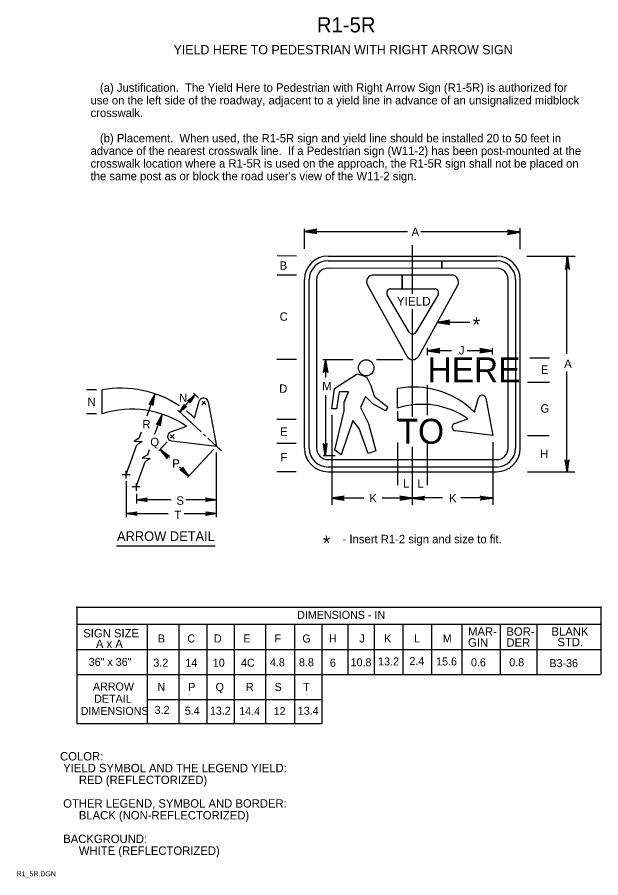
# Model space of a CAD drawing. Extents: x 0.013 to 0.186, y 0.004 to 0.259.
import ezdxf

# ---------------------------------------------------------------- set-up
doc = ezdxf.new("R2010")
doc.units = 0
for name, color, linetype in [('1', 7, 'Continuous'), ('2', 7, 'Continuous'), ('3', 7, 'Continuous')]:
    doc.layers.add(name, color=color, linetype=linetype)

# ---------------------------------------------------------------- blocks, each defined once
blk = doc.blocks.new('RARROW')
at = {"layer": '3'}
for p, q in [((-2.156, 0.28500000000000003), (-2.2665, 0.384625)), ((-2.2665, 0.384625), (0, 0)), ((0, 0), (-2.2665, -0.379125)), ((-2.156, 0.28500000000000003), (-2.075625, 0.12075)), ((0, 0), (-2.156, 0.28500000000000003)), ((-2.14975, -0.2705), (0, 0)), ((-2.075625, 0.12075), (0, 0)), ((0, 0), (-2.074, -0.108)), ((-2.2665, -0.379125), (-2.14975, -0.2705)), ((-2.074, -0.108), (-2.14975, -0.2705))]:
    blk.add_line(p, q, dxfattribs=at)

msp = doc.modelspace()

# ---------------------------------------------------------------- linework, layer by layer
at = {"layer": '1'}
for p, q in [((0.1299704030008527, 0.19165034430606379), (0.1299704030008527, 0.17719405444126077)), ((0.10497040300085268, 0.18840013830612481), (0.15497040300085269, 0.18840013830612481)), ((0.10497040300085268, 0.18700013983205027), (0.13877004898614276, 0.18700013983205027)), ((0.13877004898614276, 0.18470013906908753), (0.13877004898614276, 0.18700013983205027)), ((0.13877004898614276, 0.18700013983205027), (0.15497040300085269, 0.18700013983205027)), ((0.13877004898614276, 0.18700013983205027), (0.13877004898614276, 0.18470013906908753)), ((0.17583661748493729, 0.159368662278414), (0.17583661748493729, 0.1883907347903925)), ((0.13877004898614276, 0.18470013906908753), (0.10497040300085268, 0.18480013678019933)), ((0.15497040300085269, 0.18480013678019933), (0.13877004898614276, 0.18470013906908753)), ((0.09797040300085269, 0.1314001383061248), (0.09797040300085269, 0.1814001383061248)), ((0.0993704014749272, 0.1314001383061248), (0.0993704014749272, 0.1814001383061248)), ((0.10157040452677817, 0.1814001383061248), (0.10157040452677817, 0.1314001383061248)), ((0.12695739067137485, 0.18275925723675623), (0.11844506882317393, 0.18275925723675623)), ((0.12695739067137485, 0.18275925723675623), (0.12695739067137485, 0.1786672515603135)), ((0.12695739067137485, 0.1786672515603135), (0.12695739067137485, 0.18275925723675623)), ((0.14164213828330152, 0.18275925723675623), (0.12695739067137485, 0.18275925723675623)), ((0.1583704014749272, 0.1314001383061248), (0.1583704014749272, 0.1814001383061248)), ((0.16057040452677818, 0.1814001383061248), (0.16057040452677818, 0.1314001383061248)), ((0.1619704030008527, 0.1314001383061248), (0.1619704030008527, 0.1814001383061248)), ((0.11665515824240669, 0.17971976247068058), (0.12829779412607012, 0.1587277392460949)), ((0.1318807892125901, 0.15873350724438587), (0.14343523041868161, 0.17972553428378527)), ((0.1290345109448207, 0.16581073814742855), (0.12256011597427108, 0.17690969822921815)), ((0.12356959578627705, 0.1786672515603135), (0.12695739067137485, 0.1786672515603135)), ((0.12695739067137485, 0.1786672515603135), (0.1366024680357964, 0.1786672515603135)), ((0.13760862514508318, 0.1769040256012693), (0.13105014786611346, 0.16580505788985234)), ((0.1299704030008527, 0.17266413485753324), (0.1299704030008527, 0.14069405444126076)), ((0.1343704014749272, 0.16113755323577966), (0.1343704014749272, 0.15902658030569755)), ((0.15367040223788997, 0.16113755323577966), (0.15367040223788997, 0.159173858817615)), ((0.10418082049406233, 0.15767875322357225), (0.10418082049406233, 0.1523317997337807)), ((0.17583661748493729, 0.12438007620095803), (0.17583661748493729, 0.15414217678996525)), ((0.037975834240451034, 0.14158751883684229), (0.037975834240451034, 0.14866249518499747)), ((0.12557040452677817, 0.1432245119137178), (0.12557040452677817, 0.14905287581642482)), ((0.1343704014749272, 0.15013301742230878), (0.1343704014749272, 0.14115158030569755)), ((0.05131555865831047, 0.14101027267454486), (0.053627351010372, 0.1475216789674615)), ((0.06557366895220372, 0.1472377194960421), (0.06090879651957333, 0.14223526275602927)), ((0.06657751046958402, 0.14630162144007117), (0.06509436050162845, 0.1476846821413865)), ((0.10418082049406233, 0.14710061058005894), (0.10418082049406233, 0.1291787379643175)), ((0.14839427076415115, 0.14211684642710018), (0.14957667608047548, 0.14633188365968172)), ((0.15178639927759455, 0.1461920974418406), (0.1538704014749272, 0.1351952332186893)), ((0.06538158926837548, 0.14031934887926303), (0.06678335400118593, 0.14531636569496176)), ((0.06850288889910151, 0.14533850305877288), (0.067521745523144, 0.14428635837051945)), ((0.06870447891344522, 0.14431818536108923), (0.06760489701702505, 0.1453435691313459)), ((0.06943503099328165, 0.14514862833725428), (0.0719358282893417, 0.13195238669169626)), ((0.05365240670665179, 0.1355681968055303), (0.055758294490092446, 0.14149963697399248)), ((0.06730165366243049, 0.13627382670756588), (0.060429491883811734, 0.14268222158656)), ((0.10607040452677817, 0.14129963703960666), (0.10607040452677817, 0.11455085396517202)), ((0.12557040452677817, 0.14236577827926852), (0.12557040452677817, 0.13952658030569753)), ((0.14246136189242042, 0.13870164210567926), (0.14643814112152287, 0.14012317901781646)), ((0.048952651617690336, 0.13435490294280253), (0.049616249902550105, 0.13622399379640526)), ((0.0630171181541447, 0.1378659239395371), (0.05824498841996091, 0.13616008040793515)), ((0.05937472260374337, 0.13431328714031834), (0.058275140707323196, 0.1353386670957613)), ((0.059300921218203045, 0.13547059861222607), (0.05828654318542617, 0.13438281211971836)), ((0.06867434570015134, 0.13499376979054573), (0.0680398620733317, 0.13558543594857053)), ((0.1538704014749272, 0.1351952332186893), (0.14275494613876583, 0.1365070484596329)), ((0.057226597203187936, 0.1332461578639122), (0.054750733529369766, 0.13059112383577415)), ((0.05859728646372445, 0.13352656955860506), (0.0719358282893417, 0.13195238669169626)), ((0.07335446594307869, 0.13062948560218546), (0.06933296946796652, 0.13437959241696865)), ((0.12557040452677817, 0.13311092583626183), (0.12557040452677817, 0.12040158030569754)), ((0.1343704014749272, 0.1337316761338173), (0.1343704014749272, 0.12040158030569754)), ((0.1538704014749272, 0.13321104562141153), (0.1538704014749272, 0.11455085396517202)), ((0.04512848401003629, 0.12358373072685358), (0.04826671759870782, 0.1324228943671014)), ((0.05148564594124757, 0.12946528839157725), (0.05201389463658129, 0.13095315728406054)), ((0.05808554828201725, 0.1285094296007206), (0.05526351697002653, 0.1311410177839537)), ((0.07114570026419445, 0.13110507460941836), (0.0632636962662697, 0.1226526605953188)), ((0.1299704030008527, 0.13183852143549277), (0.1299704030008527, 0.12040158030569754)), ((0.0719358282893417, 0.11094833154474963), (0.0719358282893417, 0.13011337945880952)), ((0.10497040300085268, 0.12800013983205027), (0.15497040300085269, 0.12800013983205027)), ((0.04512848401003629, 0.12358373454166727), (0.045927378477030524, 0.12583390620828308)), ((0.048203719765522, 0.12022138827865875), (0.050746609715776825, 0.1273837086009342)), ((0.06377647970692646, 0.12320255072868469), (0.06093276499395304, 0.12585435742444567)), ((0.15497040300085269, 0.12580013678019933), (0.10497040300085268, 0.12580013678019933)), ((0.04392848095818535, 0.12358373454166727), (0.046241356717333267, 0.12358373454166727)), ((0.04512848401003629, 0.12238373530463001), (0.04512848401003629, 0.12469660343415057)), ((0.10497040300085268, 0.1244001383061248), (0.15497040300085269, 0.1244001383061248)), ((0.04512848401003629, 0.12162700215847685), (0.04512848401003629, 0.11094833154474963)), ((0.046856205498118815, 0.12000948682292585), (0.04916908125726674, 0.12000948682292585)), ((0.04812848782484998, 0.11873720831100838), (0.04812848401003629, 0.12105008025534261)), ((0.1299704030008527, 0.12040158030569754), (0.1299704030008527, 0.11455085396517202)), ((0.04812848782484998, 0.11784634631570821), (0.04812848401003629, 0.11497867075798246)), ((0.04812848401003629, 0.11614702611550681), (0.0584700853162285, 0.11614702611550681)), ((0.06280007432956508, 0.11614702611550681), (0.0719358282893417, 0.11614702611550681)), ((0.04512848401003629, 0.11202829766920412), (0.05759046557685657, 0.11202829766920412)), ((0.06230007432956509, 0.11202829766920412), (0.0719358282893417, 0.11202829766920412))]:
    msp.add_line(p, q, dxfattribs=at)
for points in [[(0.048952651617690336, 0.13435490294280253), (0.04748751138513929, 0.1334761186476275), (0.04984949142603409, 0.13332854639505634), (0.048388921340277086, 0.13237950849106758)], [(0.05148564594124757, 0.12946528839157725), (0.04986581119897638, 0.12849371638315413), (0.05222779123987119, 0.12834614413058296), (0.050746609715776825, 0.1273837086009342)]]:
    msp.add_lwpolyline(points, dxfattribs=at)
for centre, radius, start, end in [((0.10497040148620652, 0.18140013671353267), 0.007, 90, 180), ((0.10497040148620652, 0.18140013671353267), 0.005599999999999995, 90, 180), ((0.15497040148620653, 0.18140013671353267), 0.007, 0, 90), ((0.15497040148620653, 0.18140013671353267), 0.005599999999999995, 0, 90), ((0.10497040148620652, 0.18140013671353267), 0.003400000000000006, 90, 180), ((0.15497040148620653, 0.18140013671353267), 0.003400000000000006, 0, 90), ((0.11844506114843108, 0.18071248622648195), 0.0020467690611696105, 90, 209.0137077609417), ((0.14164213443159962, 0.18071248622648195), 0.002046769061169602, 331.17072672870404, 90.00000000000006), ((0.12356959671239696, 0.1774985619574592), 0.001168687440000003, 90, 210.25643716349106), ((0.13660246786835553, 0.1774985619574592), 0.0011686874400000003, 329.42077312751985, 90), ((0.1300439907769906, 0.16639960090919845), 0.0011686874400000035, 210.25642921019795, 329.4207751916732), ((0.13008769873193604, 0.15972045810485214), 0.0020467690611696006, 209.01370432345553, 331.17072804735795), ((0.04360638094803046, 0.11797475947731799), 0.031200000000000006, 56.42167073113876, 100.39692240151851), ((0.13042258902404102, 0.12399920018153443), 0.025519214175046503, 45.23173570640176, 100.96086908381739), ((0.06808773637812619, 0.14489329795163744), 0.001371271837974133, 10.730771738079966, 162.03013586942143), ((0.15066365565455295, 0.14597932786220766), 0.0011427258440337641, 10.730771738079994, 162.0299160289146), ((0.1329186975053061, 0.12091213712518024), 0.023491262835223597, 54.86468755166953, 108.228636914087), ((0.0467329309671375, 0.11440320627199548), 0.028560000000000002, 55.237597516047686, 107.85572056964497), ((0.04360638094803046, 0.11797475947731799), 0.031200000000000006, 45.73937252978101, 51.622948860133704), ((0.14288887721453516, 0.1376418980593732), 0.001142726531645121, 111.96987060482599, 263.2692347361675), ((0.05875800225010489, 0.13488838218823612), 0.001371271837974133, 111.96986876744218, 263.2692328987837), ((0.10497040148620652, 0.13140013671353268), 0.007, 180, 270), ((0.10497040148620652, 0.13140013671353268), 0.005599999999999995, 180, 270), ((0.10497040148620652, 0.13140013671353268), 0.003400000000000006, 180, 270), ((0.15497040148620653, 0.13140013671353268), 0.007, 270, 0), ((0.15497040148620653, 0.13140013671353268), 0.005599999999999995, 270, 0), ((0.15497040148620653, 0.13140013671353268), 0.003400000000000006, 270, 0)]:
    msp.add_arc(centre, radius, start, end, dxfattribs=at)
at = {"layer": '3'}
for p, q in [((0.1619704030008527, 0.19042776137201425), (0.16197687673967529, 0.19670993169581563)), ((0.09797256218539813, 0.19049372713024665), (0.09797876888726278, 0.19651637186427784)), ((0.09797792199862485, 0.1956933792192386), (0.12853636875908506, 0.1956933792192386)), ((0.13245412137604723, 0.1956933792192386), (0.16197582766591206, 0.1956933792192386)), ((0.09562044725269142, 0.18840256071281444), (0.08985416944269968, 0.1884085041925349)), ((0.16396162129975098, 0.18839470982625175), (0.17822077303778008, 0.18837407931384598)), ((0.0956145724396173, 0.1827025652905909), (0.08984829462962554, 0.18270850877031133)), ((0.1374132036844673, 0.1687847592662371), (0.14706559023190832, 0.16879470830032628)), ((0.1343704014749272, 0.1603423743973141), (0.1415955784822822, 0.16034982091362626)), ((0.1462718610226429, 0.16035463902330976), (0.15376505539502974, 0.1603623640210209)), ((0.09558880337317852, 0.15770257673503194), (0.08982252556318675, 0.15770852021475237)), ((0.10347123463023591, 0.15767828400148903), (0.11243165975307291, 0.15768751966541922)), ((0.1193952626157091, 0.15769469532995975), (0.12711765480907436, 0.1577026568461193)), ((0.17063060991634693, 0.15808764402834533), (0.16486433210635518, 0.1580935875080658)), ((0.16412330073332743, 0.15099704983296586), (0.17062329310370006, 0.15098764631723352)), ((0.036297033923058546, 0.1486642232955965), (0.03330007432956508, 0.14866731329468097)), ((0.03628973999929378, 0.14158925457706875), (0.03330007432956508, 0.1415923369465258)), ((0.09557045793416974, 0.13990258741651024), (0.08980418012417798, 0.1399085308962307)), ((0.09556314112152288, 0.13280258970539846), (0.08979686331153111, 0.1328085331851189)), ((0.1641004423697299, 0.13519706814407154), (0.17060043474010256, 0.13518766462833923)), ((0.10350060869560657, 0.12917829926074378), (0.10707144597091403, 0.12918198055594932)), ((0.09555448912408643, 0.12440984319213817), (0.08978821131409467, 0.12441578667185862)), ((0.1640848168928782, 0.12439707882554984), (0.1781281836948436, 0.12437676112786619)), ((0.10607040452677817, 0.11667455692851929), (0.11562591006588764, 0.11667455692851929)), ((0.12098599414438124, 0.11667455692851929), (0.1299704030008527, 0.11667455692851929)), ((0.13895481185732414, 0.11667455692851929), (0.1299704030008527, 0.11667455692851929)), ((0.1538704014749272, 0.11667455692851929), (0.14431489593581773, 0.11667455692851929)), ((0.042280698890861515, 0.10243853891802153), (0.07148671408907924, 0.10243853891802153)), ((0.030510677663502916, 0.08444028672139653), (0.030510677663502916, 0.04959498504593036)), ((0.18586708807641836, 0.08444028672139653), (0.18586708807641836, 0.06432524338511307)), ((0.03025, 0.08425), (0.18575, 0.08425)), ((0.18586708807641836, 0.07905550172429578), (0.030510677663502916, 0.07905550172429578)), ((0.051353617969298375, 0.07905550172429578), (0.051353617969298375, 0.04959498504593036)), ((0.15600656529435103, 0.07905550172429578), (0.15600656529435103, 0.06432524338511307)), ((0.16693973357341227, 0.07905550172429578), (0.16693973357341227, 0.06432524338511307)), ((0.03025, 0.07162500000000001), (0.18575, 0.07162500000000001)), ((0.0305, 0.06425), (0.18575, 0.06425)), ((0.051250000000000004, 0.056875), (0.10312500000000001, 0.056875)), ((0.10313567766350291, 0.04959498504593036), (0.030510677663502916, 0.04959498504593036))]:
    msp.add_line(p, q, dxfattribs=at)
msp.add_lwpolyline([(0.12274691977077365, 0.14356905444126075), (0.12199691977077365, 0.14244405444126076), (0.11824691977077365, 0.14456905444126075), (0.11612191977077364, 0.14669405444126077), (0.11462191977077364, 0.14344405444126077), (0.11699691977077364, 0.13869405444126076), (0.11912191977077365, 0.13056905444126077), (0.11687191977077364, 0.12981905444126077), (0.11424691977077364, 0.13719405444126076), (0.11237191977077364, 0.13956905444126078), (0.10887191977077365, 0.12944405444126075), (0.10699691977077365, 0.13081905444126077), (0.10974691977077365, 0.14244405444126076), (0.10974691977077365, 0.14319405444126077), (0.10974691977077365, 0.14381905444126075), (0.10974691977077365, 0.14394405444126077), (0.10974691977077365, 0.14444405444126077), (0.10974691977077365, 0.14506905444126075), (0.11099691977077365, 0.14806905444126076), (0.10824691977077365, 0.14806905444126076), (0.10749691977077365, 0.14306905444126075), (0.10612191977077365, 0.14306905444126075), (0.10687191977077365, 0.14906905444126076), (0.11362191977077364, 0.15344405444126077), (0.11549691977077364, 0.15281905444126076), (0.11649691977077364, 0.15231905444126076), (0.11762191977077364, 0.14994405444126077), (0.11862191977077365, 0.14681905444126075)], close=True, dxfattribs=at)
for points in [[(0.06076067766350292, 0.07905550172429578), (0.06076067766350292, 0.04959498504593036)], [(0.06901067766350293, 0.07905550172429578), (0.06901067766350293, 0.04959498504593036)], [(0.07713567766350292, 0.07905550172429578), (0.07713567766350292, 0.04959498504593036)], [(0.08638567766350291, 0.07905550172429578), (0.08638567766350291, 0.04959498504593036)], [(0.09501067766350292, 0.07905550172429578), (0.09501067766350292, 0.04959498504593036)], [(0.10313567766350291, 0.07905550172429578), (0.10313567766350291, 0.04959498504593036)], [(0.11088567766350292, 0.07905550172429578), (0.11088567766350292, 0.06425)], [(0.11863567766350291, 0.07905550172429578), (0.11863567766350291, 0.06432524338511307)], [(0.1271587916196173, 0.07905550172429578), (0.1271587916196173, 0.06432524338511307)], [(0.1356819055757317, 0.07905550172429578), (0.1356819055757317, 0.06432524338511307)], [(0.14462161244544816, 0.07905550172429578), (0.14462161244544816, 0.06432524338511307)]]:
    msp.add_lwpolyline(points, dxfattribs=at)
msp.add_ellipse((0.11629798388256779, 0.15522478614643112), major_axis=(-4.395448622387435e-19, -0.0023927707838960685), ratio=0.9570312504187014, dxfattribs=at)

# ---------------------------------------------------------------- block references
for p, xscale, yscale, rotation in [((0.09787191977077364, 0.19569405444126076), 0.0016545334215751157, -0.001636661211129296, -179.9170828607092), ((0.16199691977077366, 0.19544405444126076), 0.0016545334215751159, -0.0016366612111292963, 0.08291713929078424), ((0.17599691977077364, 0.18819405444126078), 0.0016545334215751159, -0.0016366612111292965, 89.91708286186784), ((0.13737191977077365, 0.16869405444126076), 0.0016545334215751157, -0.001636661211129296, -179.9170828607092), ((0.13437191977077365, 0.16031905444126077), 0.0016545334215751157, -0.001636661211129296, -179.9170828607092), ((0.15374691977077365, 0.16031905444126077), 0.0016545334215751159, -0.0016366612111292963, 0.08291713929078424), ((0.10424691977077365, 0.15756905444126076), 0.0016545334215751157, 0.0016366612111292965, 90.08291713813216), ((0.0535133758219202, 0.1472357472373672), 0.0014063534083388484, 0.001391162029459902, 70.99488834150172), ((0.0655133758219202, 0.14711074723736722), 0.001195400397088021, 0.0011824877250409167, 46.974569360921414), ((0.0608883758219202, 0.14211074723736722), 0.0011954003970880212, 0.0011824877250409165, -133.0384279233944), ((0.0556383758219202, 0.1412357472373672), 0.0014063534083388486, 0.0013911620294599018, 71.90784527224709), ((0.10412191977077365, 0.12906905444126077), 0.0016545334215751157, -0.0016366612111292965, -90.08291713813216), ((0.0552633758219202, 0.1308607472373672), 0.0014063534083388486, 0.0013911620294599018, 137.91340924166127), ((0.17587191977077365, 0.12419405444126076), 0.0016545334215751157, -0.0016366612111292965, -90.08291713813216), ((0.0636383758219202, 0.12311074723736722), 0.0014063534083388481, 0.0013911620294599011, -45.6478760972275), ((0.0481383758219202, 0.11611074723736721), 0.0014063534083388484, 0.001391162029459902, 179.91708286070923), ((0.0718883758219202, 0.11611074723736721), 0.0014063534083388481, 0.0013911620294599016, -0.08291713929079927), ((0.10599691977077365, 0.11656905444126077), 0.0016545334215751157, -0.001636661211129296, -179.9170828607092), ((0.12999691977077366, 0.11656905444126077), 0.0016545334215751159, -0.0016366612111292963, 0.08291713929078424), ((0.12987191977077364, 0.11656905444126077), 0.0016545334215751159, 0.0016366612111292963, 179.91708286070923), ((0.15387191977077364, 0.11656905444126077), 0.0016545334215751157, 0.001636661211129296, -0.08291713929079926), ((0.0451383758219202, 0.1119857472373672), 0.0014063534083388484, 0.001391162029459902, 179.91708286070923), ((0.0718883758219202, 0.1119857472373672), 0.0014063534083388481, 0.0013911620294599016, -0.08291713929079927)]:
    msp.add_blockref('RARROW', p, dxfattribs=dict(at, xscale=xscale, yscale=yscale, rotation=rotation))

# ---------------------------------------------------------------- texts
at = {"layer": '1'}
for s, height, p in [('R1-5R', 0.0045000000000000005, (0.10166804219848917, 0.25475000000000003)), ('YIELD HERE TO PEDESTRIAN WITH RIGHT ARROW SIGN', 0.00275025, (0.05916804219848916, 0.24825)), ('HERE', 0.007413, (0.13449691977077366, 0.15094405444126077)), ('TO', 0.007413, (0.12562191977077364, 0.13269405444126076)), ('- Insert R1-2 sign and size to fit.', 0.0024997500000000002, (0.10928008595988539, 0.10318778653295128)), ('COLOR: ', 0.0024997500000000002, (0.025500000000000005, 0.03874825)), (' YIELD SYMBOL AND THE LEGEND YIELD:', 0.0024997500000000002, (0.025500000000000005, 0.0352485)), ('      RED (REFLECTORIZED)', 0.0024997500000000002, (0.025500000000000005, 0.03174875)), (' OTHER LEGEND, SYMBOL AND BORDER:', 0.0024997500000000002, (0.025500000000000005, 0.02474925)), ('      BLACK (NON-REFLECTORIZED)', 0.0024997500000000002, (0.025500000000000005, 0.021249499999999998)), (' BACKGROUND:', 0.0024997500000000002, (0.025500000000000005, 0.01425)), ('      WHITE (REFLECTORIZED)', 0.0024997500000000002, (0.025500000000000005, 0.010750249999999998)), ('R1_5R.DGN', 0.0015, (0.012625, 0.004375))]:
    msp.add_text(s, height=height, dxfattribs=at).set_placement(p)
for rotation, p in [(358, (0.14774691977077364, 0.16594405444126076)), (2, (0.10353008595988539, 0.10106278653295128))]:
    msp.add_text('*', height=0.00432, rotation=rotation, dxfattribs=at).set_placement(p)
at = {"layer": '2'}
for s, p in [('   (a) Justification.  The Yield Here to Pedestrian with Right Arrow Sign (R1-5R) is authorized for', (0.03454304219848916, 0.23712524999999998)), ('use on the left side of the roadway, adjacent to a yield line in advance of an unsignalized midblock', (0.03454304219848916, 0.23337549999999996)), ('crosswalk.', (0.03454304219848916, 0.22962575)), ('   (b) Placement.  When used, the R1-5R sign and yield line should be installed 20 to 50 feet in', (0.03454304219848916, 0.22212624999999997)), ('advance of the nearest crosswalk line.  If a Pedestrian sign (W11-2) has been post-mounted at the', (0.03454304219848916, 0.21837649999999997)), ('crosswalk location where a R1-5R is used on the approach, the R1-5R sign shall not be placed on ', (0.03454304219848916, 0.21462674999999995)), ("the same post as or block the road user's view of the W11-2 sign.", (0.03454304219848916, 0.21087699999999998))]:
    msp.add_text(s, height=0.0024997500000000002, dxfattribs=at).set_placement(p)
at = {"layer": '3'}
for s, rotation, p in [('A', 0.08291666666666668, (0.12974691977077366, 0.19431905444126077)), ('B', 0.08291666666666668, (0.09062191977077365, 0.18431905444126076)), ('C', 359.9170833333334, (0.09062191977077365, 0.16919405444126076)), ('J', 359.9170833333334, (0.14374691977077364, 0.15919405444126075)), ('E', 359.9170833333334, (0.16812191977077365, 0.15344405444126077)), ('A', 359.9170833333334, (0.17499691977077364, 0.15519405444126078)), ('M', 359.9170833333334, (0.10324691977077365, 0.14856905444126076)), ('D', 0.08291666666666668, (0.09049691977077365, 0.14781905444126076)), ('N', 359.9170833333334, (0.0336383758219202, 0.14386074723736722)), ('N', 359.9170833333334, (0.0607633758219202, 0.14511074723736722)), ('G', 0.08291666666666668, (0.16799691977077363, 0.14194405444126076)), ('R', 359.9170833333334, (0.0498883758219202, 0.1372357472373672)), ('E', 359.9170833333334, (0.09074691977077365, 0.13506905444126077)), ('Q', 359.9170833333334, (0.0522633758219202, 0.1319857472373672)), ('H', 359.9170833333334, (0.16787191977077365, 0.12844405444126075)), ('P', 359.9170833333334, (0.0587633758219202, 0.1256107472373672)), ('F', 0.08291666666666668, (0.09087191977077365, 0.12744405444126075)), ('L', 0.08291666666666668, (0.12724691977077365, 0.11969405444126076)), ('L', 359.9170833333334, (0.13149691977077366, 0.11969405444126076)), ('K', 0.08291666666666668, (0.11724691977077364, 0.11531905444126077)), ('K', 359.9170833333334, (0.14087191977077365, 0.11531905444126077)), ('S', 359.9170833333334, (0.0600133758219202, 0.11461074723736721)), ('T', 359.9170833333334, (0.0593883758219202, 0.1103607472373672))]:
    msp.add_text(s, height=0.0024997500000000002, rotation=rotation, dxfattribs=at).set_placement(p)
for s, height, p in [('YIELD', 0.0025972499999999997, (0.12537191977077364, 0.17369405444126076)), ('ARROW DETAIL', 0.00285, (0.0423883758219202, 0.10386074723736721)), ('DIMENSIONS - IN', 0.0023752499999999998, (0.09581659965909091, 0.08075)), ('SIGN SIZE', 0.0024997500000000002, (0.032375, 0.07525)), ('MAR-', 0.0024997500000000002, (0.1465, 0.07575)), ('BOR-', 0.0024997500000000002, (0.15787500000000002, 0.07575)), ('BLANK', 0.0024997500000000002, (0.17125, 0.07575)), ('A x A', 0.0024997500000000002, (0.036125, 0.072125)), ('B', 0.0023752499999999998, (0.0545, 0.07375)), ('C', 0.0023752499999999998, (0.06325, 0.07375)), ('D', 0.0023752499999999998, (0.07112500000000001, 0.07375)), ('E', 0.0023752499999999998, (0.079875, 0.07375)), ('F', 0.0023752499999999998, (0.089125, 0.07375)), ('G', 0.0023752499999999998, (0.097375, 0.07375)), ('H', 0.0023752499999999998, (0.10525, 0.07375)), ('J', 0.0023752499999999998, (0.11425, 0.07375)), ('K', 0.0023752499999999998, (0.121625, 0.07375)), ('L', 0.0023752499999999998, (0.1305, 0.07375)), ('M', 0.0023752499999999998, (0.139, 0.07375)), ('GIN', 0.0024997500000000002, (0.1465, 0.0725)), ('DER', 0.0024997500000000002, (0.15787500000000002, 0.0725)), ('STD.', 0.0024997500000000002, (0.17300000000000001, 0.072625)), ('36" x 36"', 0.0023752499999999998, (0.033995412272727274, 0.06681237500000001)), ('3.2', 0.0023752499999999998, (0.05316997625, 0.06656237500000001)), ('14', 0.0023752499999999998, (0.06266578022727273, 0.06656237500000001)), ('10', 0.0023752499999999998, (0.07079725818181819, 0.06656237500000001)), ('4C', 0.0023752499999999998, (0.07916457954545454, 0.06656237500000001)), ('4.8', 0.0023752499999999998, (0.08773055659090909, 0.06668737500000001)), ('8.8', 0.0023752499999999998, (0.0963555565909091, 0.06668737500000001)), ('6', 0.0023752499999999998, (0.10552206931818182, 0.06656237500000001)), ('10.8', 0.0023752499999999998, (0.11167320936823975, 0.06668737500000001)), ('13.2', 0.0023752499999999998, (0.11982520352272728, 0.06693737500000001)), ('2.4', 0.0023752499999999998, (0.12910699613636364, 0.06706237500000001)), ('15.6', 0.0023752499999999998, (0.13702373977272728, 0.06693737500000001)), ('0.6', 0.0023752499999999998, (0.14736851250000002, 0.06668737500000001)), ('0.8', 0.0023752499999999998, (0.1587305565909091, 0.06668737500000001)), ('B3-36', 0.0023752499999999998, (0.17062642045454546, 0.066437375)), ('ARROW', 0.0023752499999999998, (0.035250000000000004, 0.059500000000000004)), ('N', 0.0023752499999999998, (0.054375, 0.059375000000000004)), ('P', 0.0023752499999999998, (0.0635, 0.059375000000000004)), ('Q', 0.0023752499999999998, (0.07162500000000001, 0.059375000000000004)), ('R', 0.0023752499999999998, (0.080625, 0.059375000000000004)), ('S', 0.0023752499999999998, (0.089125, 0.059375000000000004)), ('T', 0.0023752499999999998, (0.097625, 0.059375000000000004)), ('DETAIL', 0.0023752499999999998, (0.035625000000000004, 0.055875)), ('DIMENSIONS', 0.0023752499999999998, (0.031625, 0.05225)), ('3.2', 0.0023752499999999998, (0.05354497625, 0.052562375)), ('5.4', 0.0023752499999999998, (0.062481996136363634, 0.052312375)), ('13.2', 0.0023752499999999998, (0.06995020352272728, 0.052312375)), ('14.4', 0.0023752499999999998, (0.07863408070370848, 0.052187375)), ('12', 0.0023752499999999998, (0.0888537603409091, 0.052187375)), ('13.4', 0.0023752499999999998, (0.09600290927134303, 0.052312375))]:
    msp.add_text(s, height=height, dxfattribs=at).set_placement(p)

doc.saveas('drawing.dxf')
